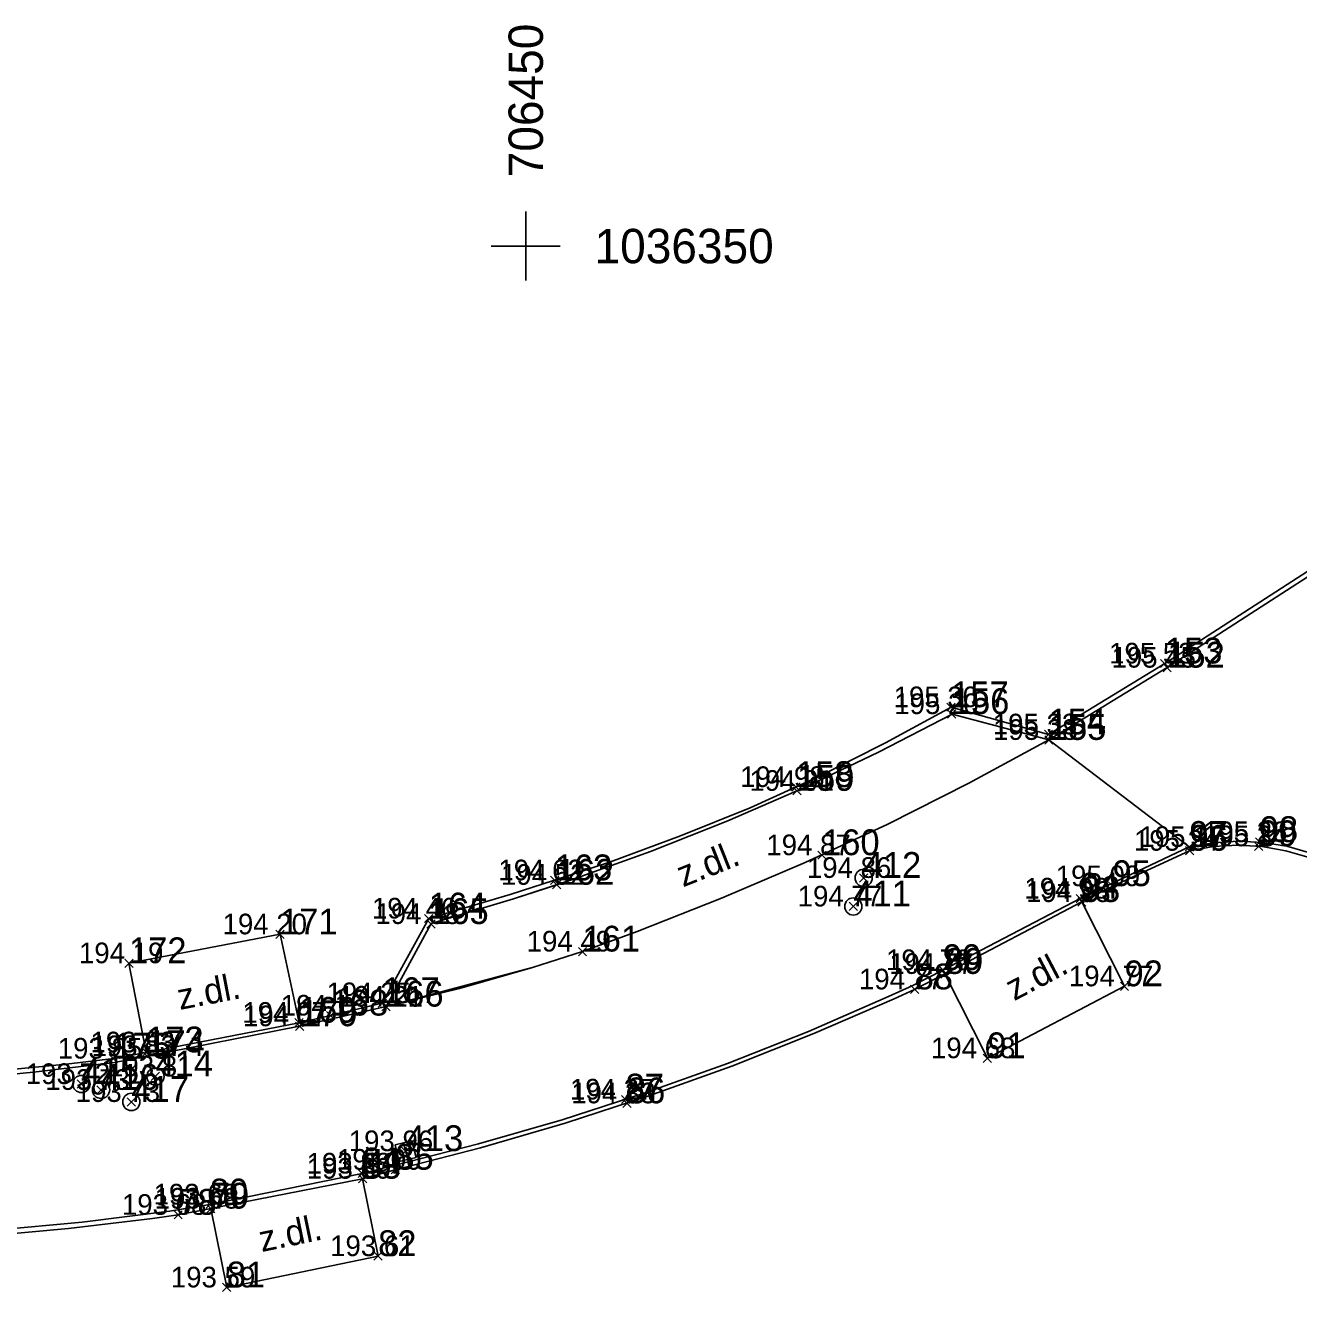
# Model space of a CAD drawing. Extents: x -706861 to -706379, y -1036456 to -1036201.
# Drawn here: x -706464.54 to -706427.54, y -1036380.38 to -1036343.59 of the extents above; entities that cross this region are included whole.
import ezdxf

# ---------------------------------------------------------------- set-up
doc = ezdxf.new("R2010")
doc.units = 0
for name, color, linetype in [('18_popisy', 7, 'Continuous'), ('29_vodovod', 7, 'Continuous'), ('30_kanalizace splašková', 7, 'Continuous'), ('40_plochy', 7, 'Continuous'), ('51_body polohopisu_značky', 7, 'Continuous'), ('52_body polohopisu_čísla', 7, 'Continuous'), ('53_body polohopisu_výšky', 7, 'Continuous'), ('54_body polohopisu_čísla nadbytečné pro kreslení', 7, 'Continuous'), ('5_rozhraní ploch', 7, 'Continuous'), ('60_mapový rám_legenda', 7, 'Continuous')]:
    doc.layers.add(name, color=color, linetype=linetype)

msp = doc.modelspace()

# ---------------------------------------------------------------- linework, layer by layer
at = {"layer": '29_vodovod'}
for centre in [(-706440.18, -1036368.36), (-706462.91, -1036374.35), (-706460.76, -1036374.13)]:
    msp.add_circle(centre, 0.25, dxfattribs=at)
at = {"layer": '30_kanalizace splašková'}
msp.add_line((-706453.55, -1036376.057), (-706453.43, -1036376.543), dxfattribs=at)
msp.add_lwpolyline([(-706453.794, -1036376.118), (-706453.673, -1036376.604), (-706453.187, -1036376.483), (-706453.307, -1036375.997)], close=True, dxfattribs=at)
for centre in [(-706440.48, -1036369.19), (-706462.34, -1036374.52), (-706461.46, -1036374.87)]:
    msp.add_circle(centre, 0.25, dxfattribs=at)
at = {"layer": '40_plochy'}
for points in [[(-706423.8, -1036357.36), (-706431.36, -1036362.25), (-706434.8, -1036364.35), (-706430.72, -1036367.46), (-706430.01, -1036367.34), (-706429.3, -1036367.29), (-706428.58, -1036367.33), (-706427.88, -1036367.44), (-706427.19, -1036367.64)], [(-706466.82, -1036374.25), (-706464.3, -1036374.01), (-706461.95, -1036373.72), (-706461, -1036373.54), (-706456.57, -1036372.67), (-706454.06, -1036372.1), (-706449.8, -1036370.96), (-706448.35, -1036370.5), (-706446.76, -1036369.92), (-706444.31, -1036368.95), (-706441.88, -1036367.91), (-706439.48, -1036366.8), (-706437.12, -1036365.61), (-706434.8, -1036364.35), (-706430.72, -1036367.46), (-706433.89, -1036368.96), (-706437.88, -1036371.04), (-706438.75, -1036371.49), (-706439.46, -1036371.81), (-706441.78, -1036372.82), (-706444.14, -1036373.75), (-706446.53, -1036374.61), (-706448.94, -1036375.39), (-706451.37, -1036376.09), (-706453.83, -1036376.72), (-706454.75, -1036376.95), (-706459.18, -1036377.85), (-706460.35, -1036378.04), (-706462.89, -1036378.36), (-706465.43, -1036378.6)]]:
    msp.add_lwpolyline(points, dxfattribs=at)
for points in [[(-706434.8, -1036364.35), (-706437.61, -1036363.6), (-706439.75, -1036364.71), (-706441.92, -1036365.74), (-706444.13, -1036366.7), (-706446.37, -1036367.59), (-706448.64, -1036368.41), (-706450.36, -1036368.97), (-706452.75, -1036369.69), (-706454.06, -1036372.1), (-706451.92, -1036371.57), (-706449.8, -1036370.96), (-706448.35, -1036370.5), (-706446.76, -1036369.92), (-706444.31, -1036368.95), (-706441.88, -1036367.91), (-706439.48, -1036366.8), (-706437.12, -1036365.61)], [(-706433.84, -1036369.06), (-706432.6, -1036371.51), (-706436.58, -1036373.6), (-706437.82, -1036371.15)], [(-706456.58, -1036372.57), (-706457.14, -1036370), (-706461.53, -1036370.84), (-706461.03, -1036373.43)], [(-706454.74, -1036377.1), (-706454.29, -1036379.35), (-706458.69, -1036380.26), (-706459.15, -1036377.97)]]:
    msp.add_lwpolyline(points, close=True, dxfattribs=at)
at = {"layer": '51_body polohopisu_značky'}
for points in [[(-706431.55, -1036362.25), (-706431.31, -1036362.01)], [(-706431.55, -1036362.01), (-706431.31, -1036362.25)], [(-706431.48, -1036362.37), (-706431.24, -1036362.13)], [(-706431.48, -1036362.13), (-706431.24, -1036362.37)], [(-706437.76, -1036363.52), (-706437.52, -1036363.28)], [(-706437.76, -1036363.28), (-706437.52, -1036363.52)], [(-706437.74, -1036363.72), (-706437.5, -1036363.48)], [(-706437.74, -1036363.48), (-706437.5, -1036363.72)], [(-706434.93, -1036364.31), (-706434.69, -1036364.07)], [(-706434.93, -1036364.07), (-706434.69, -1036364.31)], [(-706434.92, -1036364.47), (-706434.68, -1036364.23)], [(-706434.92, -1036364.23), (-706434.68, -1036364.47)], [(-706442.27, -1036365.84), (-706442.03, -1036365.6)], [(-706442.27, -1036365.6), (-706442.03, -1036365.84)], [(-706442.24, -1036365.95), (-706442, -1036365.71)], [(-706442.24, -1036365.71), (-706442, -1036365.95)], [(-706430.84, -1036367.58), (-706430.6, -1036367.34)], [(-706430.84, -1036367.34), (-706430.6, -1036367.58)], [(-706430.83, -1036367.69), (-706430.59, -1036367.45)], [(-706430.83, -1036367.45), (-706430.59, -1036367.69)], [(-706428.82, -1036367.56), (-706428.58, -1036367.32)], [(-706428.82, -1036367.32), (-706428.58, -1036367.56)], [(-706428.79, -1036367.44), (-706428.55, -1036367.2)], [(-706428.79, -1036367.2), (-706428.55, -1036367.44)], [(-706441.51, -1036367.82), (-706441.27, -1036367.58)], [(-706441.51, -1036367.58), (-706441.27, -1036367.82)], [(-706440.3, -1036368.48), (-706440.06, -1036368.24)], [(-706440.3, -1036368.24), (-706440.06, -1036368.48)], [(-706449.28, -1036368.55), (-706449.04, -1036368.31)], [(-706449.28, -1036368.31), (-706449.04, -1036368.55)], [(-706449.22, -1036368.68), (-706448.98, -1036368.44)], [(-706449.22, -1036368.44), (-706448.98, -1036368.68)], [(-706433.07, -1036368.72), (-706432.83, -1036368.48)], [(-706433.07, -1036368.48), (-706432.83, -1036368.72)], [(-706434.01, -1036369.08), (-706433.77, -1036368.84)], [(-706434.01, -1036368.84), (-706433.77, -1036369.08)], [(-706433.96, -1036369.18), (-706433.72, -1036368.94)], [(-706433.96, -1036368.94), (-706433.72, -1036369.18)], [(-706440.6, -1036369.31), (-706440.36, -1036369.07)], [(-706440.6, -1036369.07), (-706440.36, -1036369.31)], [(-706452.94, -1036369.66), (-706452.7, -1036369.42)], [(-706452.94, -1036369.42), (-706452.7, -1036369.66)], [(-706452.87, -1036369.82), (-706452.63, -1036369.58)], [(-706452.87, -1036369.58), (-706452.63, -1036369.82)], [(-706457.26, -1036370.12), (-706457.02, -1036369.88)], [(-706457.26, -1036369.88), (-706457.02, -1036370.12)], [(-706448.47, -1036370.62), (-706448.23, -1036370.38)], [(-706448.47, -1036370.38), (-706448.23, -1036370.62)], [(-706461.65, -1036370.96), (-706461.41, -1036370.72)], [(-706461.65, -1036370.72), (-706461.41, -1036370.96)], [(-706438, -1036371.16), (-706437.76, -1036370.92)], [(-706438, -1036370.92), (-706437.76, -1036371.16)], [(-706437.94, -1036371.27), (-706437.7, -1036371.03)], [(-706437.94, -1036371.03), (-706437.7, -1036371.27)], [(-706438.82, -1036371.72), (-706438.58, -1036371.48)], [(-706438.82, -1036371.48), (-706438.58, -1036371.72)], [(-706432.72, -1036371.63), (-706432.48, -1036371.39)], [(-706432.72, -1036371.39), (-706432.48, -1036371.63)], [(-706454.29, -1036372.12), (-706454.05, -1036371.88)], [(-706454.29, -1036371.88), (-706454.05, -1036372.12)], [(-706455.79, -1036372.48), (-706455.55, -1036372.24)], [(-706455.79, -1036372.24), (-706455.55, -1036372.48)], [(-706454.18, -1036372.22), (-706453.94, -1036371.98)], [(-706454.18, -1036371.98), (-706453.94, -1036372.22)], [(-706456.71, -1036372.69), (-706456.47, -1036372.45)], [(-706456.71, -1036372.45), (-706456.47, -1036372.69)], [(-706456.69, -1036372.79), (-706456.45, -1036372.55)], [(-706456.69, -1036372.55), (-706456.45, -1036372.79)], [(-706461.15, -1036373.55), (-706460.91, -1036373.31)], [(-706461.15, -1036373.31), (-706460.91, -1036373.55)], [(-706461.12, -1036373.66), (-706460.88, -1036373.42)], [(-706461.12, -1036373.42), (-706460.88, -1036373.66)], [(-706462.1, -1036373.73), (-706461.86, -1036373.49)], [(-706462.1, -1036373.49), (-706461.86, -1036373.73)], [(-706436.71, -1036373.72), (-706436.47, -1036373.48)], [(-706436.71, -1036373.48), (-706436.47, -1036373.72)], [(-706460.88, -1036374.25), (-706460.64, -1036374.01)], [(-706460.88, -1036374.01), (-706460.64, -1036374.25)], [(-706463.03, -1036374.47), (-706462.79, -1036374.23)], [(-706463.03, -1036374.23), (-706462.79, -1036374.47)], [(-706462.46, -1036374.64), (-706462.22, -1036374.4)], [(-706462.46, -1036374.4), (-706462.22, -1036374.64)], [(-706461.58, -1036374.99), (-706461.34, -1036374.75)], [(-706461.58, -1036374.75), (-706461.34, -1036374.99)], [(-706447.22, -1036374.92), (-706446.98, -1036374.68)], [(-706447.22, -1036374.68), (-706446.98, -1036374.92)], [(-706447.18, -1036375.03), (-706446.94, -1036374.79)], [(-706447.18, -1036374.79), (-706446.94, -1036375.03)], [(-706453.61, -1036376.42), (-706453.37, -1036376.18)], [(-706453.61, -1036376.18), (-706453.37, -1036376.42)], [(-706453.91, -1036376.96), (-706453.67, -1036376.72)], [(-706453.91, -1036376.72), (-706453.67, -1036376.96)], [(-706454.87, -1036377.07), (-706454.63, -1036376.83)], [(-706454.87, -1036376.83), (-706454.63, -1036377.07)], [(-706454.86, -1036377.22), (-706454.62, -1036376.98)], [(-706454.86, -1036376.98), (-706454.62, -1036377.22)], [(-706459.3, -1036377.97), (-706459.06, -1036377.73)], [(-706459.3, -1036377.73), (-706459.06, -1036377.97)], [(-706459.27, -1036378.09), (-706459.03, -1036377.85)], [(-706459.27, -1036377.85), (-706459.03, -1036378.09)], [(-706460.22, -1036378.27), (-706459.98, -1036378.03)], [(-706460.22, -1036378.03), (-706459.98, -1036378.27)], [(-706454.41, -1036379.47), (-706454.17, -1036379.23)], [(-706454.41, -1036379.23), (-706454.17, -1036379.47)], [(-706458.81, -1036380.38), (-706458.57, -1036380.14)], [(-706458.81, -1036380.14), (-706458.57, -1036380.38)]]:
    msp.add_lwpolyline(points, dxfattribs=at)
at = {"layer": '5_rozhraní ploch'}
for points in [[(-706423.88, -1036357.26), (-706431.43, -1036362.13), (-706434.81, -1036364.19), (-706437.64, -1036363.4)], [(-706423.8, -1036357.36), (-706431.36, -1036362.25), (-706434.8, -1036364.35), (-706437.61, -1036363.6)], [(-706437.64, -1036363.4), (-706439.55, -1036364.44), (-706441.5, -1036365.42), (-706443.48, -1036366.32), (-706445.5, -1036367.14), (-706447.54, -1036367.89), (-706449.16, -1036368.43)], [(-706437.61, -1036363.6), (-706439.75, -1036364.71), (-706441.92, -1036365.74), (-706444.13, -1036366.7), (-706446.37, -1036367.59), (-706448.64, -1036368.41), (-706449.1, -1036368.56)], [(-706434.8, -1036364.35), (-706437.12, -1036365.61), (-706439.48, -1036366.8), (-706441.88, -1036367.91), (-706444.31, -1036368.95), (-706446.76, -1036369.92), (-706448.35, -1036370.5)], [(-706438.75, -1036371.49), (-706437.88, -1036371.04), (-706433.89, -1036368.96), (-706430.72, -1036367.46)], [(-706430.72, -1036367.46), (-706430.01, -1036367.34), (-706429.3, -1036367.29), (-706428.58, -1036367.33), (-706427.88, -1036367.44), (-706427.19, -1036367.64), (-706426.52, -1036367.91), (-706425.81, -1036368.3)], [(-706430.71, -1036367.57), (-706430.01, -1036367.45), (-706429.31, -1036367.41), (-706428.61, -1036367.45), (-706427.91, -1036367.57), (-706427.23, -1036367.77), (-706426.58, -1036368.04), (-706425.97, -1036368.38), (-706425.88, -1036368.44)], [(-706438.7, -1036371.6), (-706437.82, -1036371.15), (-706433.84, -1036369.06), (-706432.94, -1036368.6), (-706430.71, -1036367.57)], [(-706452.82, -1036369.54), (-706450.45, -1036368.84), (-706449.16, -1036368.43)], [(-706452.75, -1036369.69), (-706450.36, -1036368.97), (-706449.1, -1036368.56)], [(-706437.82, -1036371.15), (-706436.58, -1036373.6), (-706432.6, -1036371.51), (-706433.84, -1036369.06)], [(-706452.82, -1036369.54), (-706454.17, -1036372), (-706455.67, -1036372.36), (-706456.58, -1036372.57), (-706461.03, -1036373.43), (-706461.97, -1036373.61)], [(-706452.75, -1036369.69), (-706454.06, -1036372.1), (-706456.57, -1036372.67), (-706461, -1036373.54), (-706461.95, -1036373.72)], [(-706456.58, -1036372.57), (-706457.14, -1036370), (-706461.53, -1036370.84), (-706461.03, -1036373.43)], [(-706454.06, -1036372.1), (-706451.92, -1036371.57), (-706449.8, -1036370.96), (-706448.35, -1036370.5)], [(-706453.83, -1036376.72), (-706451.37, -1036376.09), (-706448.94, -1036375.39), (-706446.53, -1036374.61), (-706444.14, -1036373.75), (-706441.78, -1036372.82), (-706439.46, -1036371.81), (-706438.75, -1036371.49)], [(-706453.79, -1036376.84), (-706451.31, -1036376.2), (-706448.85, -1036375.49), (-706446.42, -1036374.69), (-706444.01, -1036373.83), (-706441.63, -1036372.88), (-706439.29, -1036371.87), (-706438.7, -1036371.6)], [(-706476.96, -1036374.28), (-706474.23, -1036374.34), (-706471.51, -1036374.32), (-706468.78, -1036374.22), (-706466.06, -1036374.03), (-706463.35, -1036373.77), (-706461.97, -1036373.61)], [(-706476.95, -1036374.4), (-706474.42, -1036374.48), (-706471.88, -1036374.49), (-706469.35, -1036374.41), (-706466.82, -1036374.25), (-706464.3, -1036374.01), (-706461.95, -1036373.72)], [(-706460.11, -1036378.01), (-706459.18, -1036377.85), (-706454.75, -1036376.95), (-706453.83, -1036376.72)], [(-706460.1, -1036378.15), (-706459.15, -1036377.97), (-706454.74, -1036377.1), (-706453.79, -1036376.84)], [(-706459.15, -1036377.97), (-706458.69, -1036380.26), (-706454.29, -1036379.35), (-706454.74, -1036377.1)], [(-706473.08, -1036378.83), (-706470.53, -1036378.83), (-706467.98, -1036378.76), (-706465.43, -1036378.6), (-706462.89, -1036378.36), (-706460.35, -1036378.04), (-706460.11, -1036378.01)], [(-706473.08, -1036378.93), (-706470.63, -1036378.96), (-706468.18, -1036378.9), (-706465.73, -1036378.77), (-706463.29, -1036378.55), (-706460.85, -1036378.26), (-706460.1, -1036378.15)]]:
    msp.add_lwpolyline(points, dxfattribs=at)
at = {"layer": '60_mapový rám_legenda'}
for points in [[(-706450, -1036349), (-706450, -1036350), (-706450, -1036351)], [(-706449, -1036350), (-706450, -1036350), (-706451, -1036350)]]:
    msp.add_lwpolyline(points, dxfattribs=at)

# ---------------------------------------------------------------- texts
at = {"layer": '18_popisy'}
for rotation, p in [(21.669, (-706445.429, -1036368.638)), (27.7051, (-706435.808, -1036371.947)), (10.8323, (-706460.05, -1036372.198)), (11.6851, (-706457.673, -1036379.234))]:
    msp.add_text('z.dl.', height=0.75, rotation=rotation, dxfattribs=at).set_placement(p)
at = {"layer": '52_body polohopisu_čísla'}
for s, p in [('153', (-706431.43, -1036362.13)), ('156', (-706437.62, -1036363.6)), ('155', (-706434.8, -1036364.35)), ('158', (-706442.15, -1036365.72)), ('99', (-706428.7, -1036367.44)), ('160', (-706441.39, -1036367.7)), ('96', (-706430.71, -1036367.57)), ('163', (-706449.16, -1036368.43)), ('95', (-706432.95, -1036368.6)), ('411', (-706440.48, -1036369.19)), ('164', (-706452.82, -1036369.54)), ('171', (-706457.14, -1036370)), ('172', (-706461.53, -1036370.84)), ('161', (-706448.35, -1036370.5)), ('90', (-706437.88, -1036371.04)), ('92', (-706432.6, -1036371.51)), ('166', (-706454.06, -1036372.1)), ('169', (-706456.59, -1036372.57)), ('173', (-706461.03, -1036373.43)), ('91', (-706436.59, -1036373.6)), ('86', (-706447.06, -1036374.91)), ('413', (-706453.49, -1036376.3)), ('83', (-706454.74, -1036377.1)), ('78', (-706460.1, -1036378.15)), ('82', (-706454.29, -1036379.35)), ('81', (-706458.69, -1036380.26))]:
    msp.add_text(s, height=0.75, dxfattribs=at).set_placement(p)
at = {"layer": '53_body polohopisu_výšky'}
for s, p in [('195 53 ', (-706433.048, -1036362.13)), ('195 45 ', (-706432.978, -1036362.25)), ('195 30 ', (-706439.31, -1036363.4)), ('195 20 ', (-706439.29, -1036363.6)), ('195 33 ', (-706436.428, -1036364.19)), ('195 28 ', (-706436.418, -1036364.35)), ('194 98 ', (-706443.77, -1036365.72)), ('194 91 ', (-706443.499, -1036365.83)), ('195 26 ', (-706430.321, -1036367.32)), ('194 87 ', (-706443.008, -1036367.7)), ('195 24 ', (-706432.328, -1036367.57)), ('195 17 ', (-706432.168, -1036367.46)), ('195 34 ', (-706430.318, -1036367.44)), ('194 62 ', (-706450.795, -1036368.43)), ('194 86 ', (-706441.831, -1036368.36)), ('194 52 ', (-706450.718, -1036368.56)), ('195 09 ', (-706434.599, -1036368.6)), ('194 77 ', (-706442.098, -1036369.19)), ('194 98 ', (-706435.51, -1036368.96)), ('194 98 ', (-706435.46, -1036369.06)), ('194 46 ', (-706454.471, -1036369.54)), ('194 38 ', (-706454.368, -1036369.7)), ('194 20 ', (-706458.81, -1036370)), ('194 49 ', (-706449.973, -1036370.5)), ('194 19 ', (-706462.983, -1036370.84)), ('194 76 ', (-706439.531, -1036371.04)), ('194 77 ', (-706439.438, -1036371.15)), ('194 77 ', (-706440.318, -1036371.6)), ('194 77 ', (-706434.218, -1036371.51)), ('194 25 ', (-706455.788, -1036372)), ('194 21 ', (-706455.437, -1036372.1)), ('194 18 ', (-706457.118, -1036372.36)), ('194 07 ', (-706458.234, -1036372.57)), ('194 07 ', (-706458.214, -1036372.67)), ('193 85 ', (-706463.598, -1036373.61)), ('193 83 ', (-706462.648, -1036373.43)), ('193 83 ', (-706462.618, -1036373.54)), ('194 68 ', (-706438.225, -1036373.6)), ('193 72 ', (-706464.528, -1036374.35)), ('193 81 ', (-706462.137, -1036374.13)), ('193 73 ', (-706463.958, -1036374.52)), ('193 73 ', (-706463.078, -1036374.87)), ('194 27 ', (-706448.718, -1036374.8)), ('194 33 ', (-706448.678, -1036374.91)), ('193 96 ', (-706455.143, -1036376.3)), ('193 88 ', (-706456.368, -1036376.95)), ('194 00 ', (-706455.486, -1036376.84)), ('193 89 ', (-706456.363, -1036377.1)), ('193 68 ', (-706460.815, -1036377.85)), ('193 68 ', (-706460.785, -1036377.97)), ('193 68 ', (-706461.735, -1036378.15)), ('193 61 ', (-706455.684, -1036379.35)), ('193 59 ', (-706460.313, -1036380.26))]:
    msp.add_text(s, height=0.6, dxfattribs=at).set_placement(p)
at = {"layer": '54_body polohopisu_čísla nadbytečné pro kreslení'}
for s, p in [('152', (-706431.36, -1036362.25)), ('157', (-706437.64, -1036363.4)), ('154', (-706434.81, -1036364.19)), ('159', (-706442.12, -1036365.83)), ('97', (-706430.72, -1036367.46)), ('98', (-706428.67, -1036367.32)), ('162', (-706449.1, -1036368.56)), ('412', (-706440.18, -1036368.36)), ('94', (-706433.89, -1036368.96)), ('93', (-706433.84, -1036369.06)), ('165', (-706452.75, -1036369.7)), ('89', (-706437.82, -1036371.15)), ('88', (-706438.7, -1036371.6)), ('167', (-706454.17, -1036372)), ('170', (-706456.57, -1036372.67)), ('168', (-706455.67, -1036372.36)), ('175', (-706461.98, -1036373.61)), ('174', (-706461, -1036373.54)), ('414', (-706460.76, -1036374.13)), ('415', (-706462.91, -1036374.35)), ('416', (-706462.34, -1036374.52)), ('417', (-706461.46, -1036374.87)), ('87', (-706447.1, -1036374.8)), ('84', (-706454.75, -1036376.95)), ('85', (-706453.79, -1036376.84)), ('80', (-706459.18, -1036377.85)), ('79', (-706459.15, -1036377.97))]:
    msp.add_text(s, height=0.75, dxfattribs=at).set_placement(p)
at = {"layer": '60_mapový rám_legenda'}
msp.add_text('706450', height=1, rotation=90, dxfattribs=at).set_placement((-706449.5, -1036348))
msp.add_text('1036350', height=1, dxfattribs=at).set_placement((-706448, -1036350.5))

doc.saveas('drawing.dxf')
